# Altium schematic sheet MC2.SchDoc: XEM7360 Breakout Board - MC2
size C; Author: Nick Kettman; Organization: Opal Kelly; Address1: 13500 SW 72nd Ave Ste 100; Address2: Portland, OR 97223; Address4: http://www.opalkelly.com; DocumentNumber: xxx; Revision: 1; SheetNumber: 3; SheetTotal: 3; PageSetup: Record=PageOptions¦CenterHorizontal=True¦CenterVertical=True¦PrintScale=0.53¦XCorrection=1.00¦YCorrection=1.00¦PrintKind=0¦BorderSize=5000000¦LeftOffset=0¦BottomOffset=0¦Orientation=2¦PaperLength=1000¦PaperWidth=1000¦Scale=100¦PaperSource=7¦PrintQuality=-4¦MediaType=1¦DitherType=10¦PaperKind=Letter¦PrintScaleMode=1
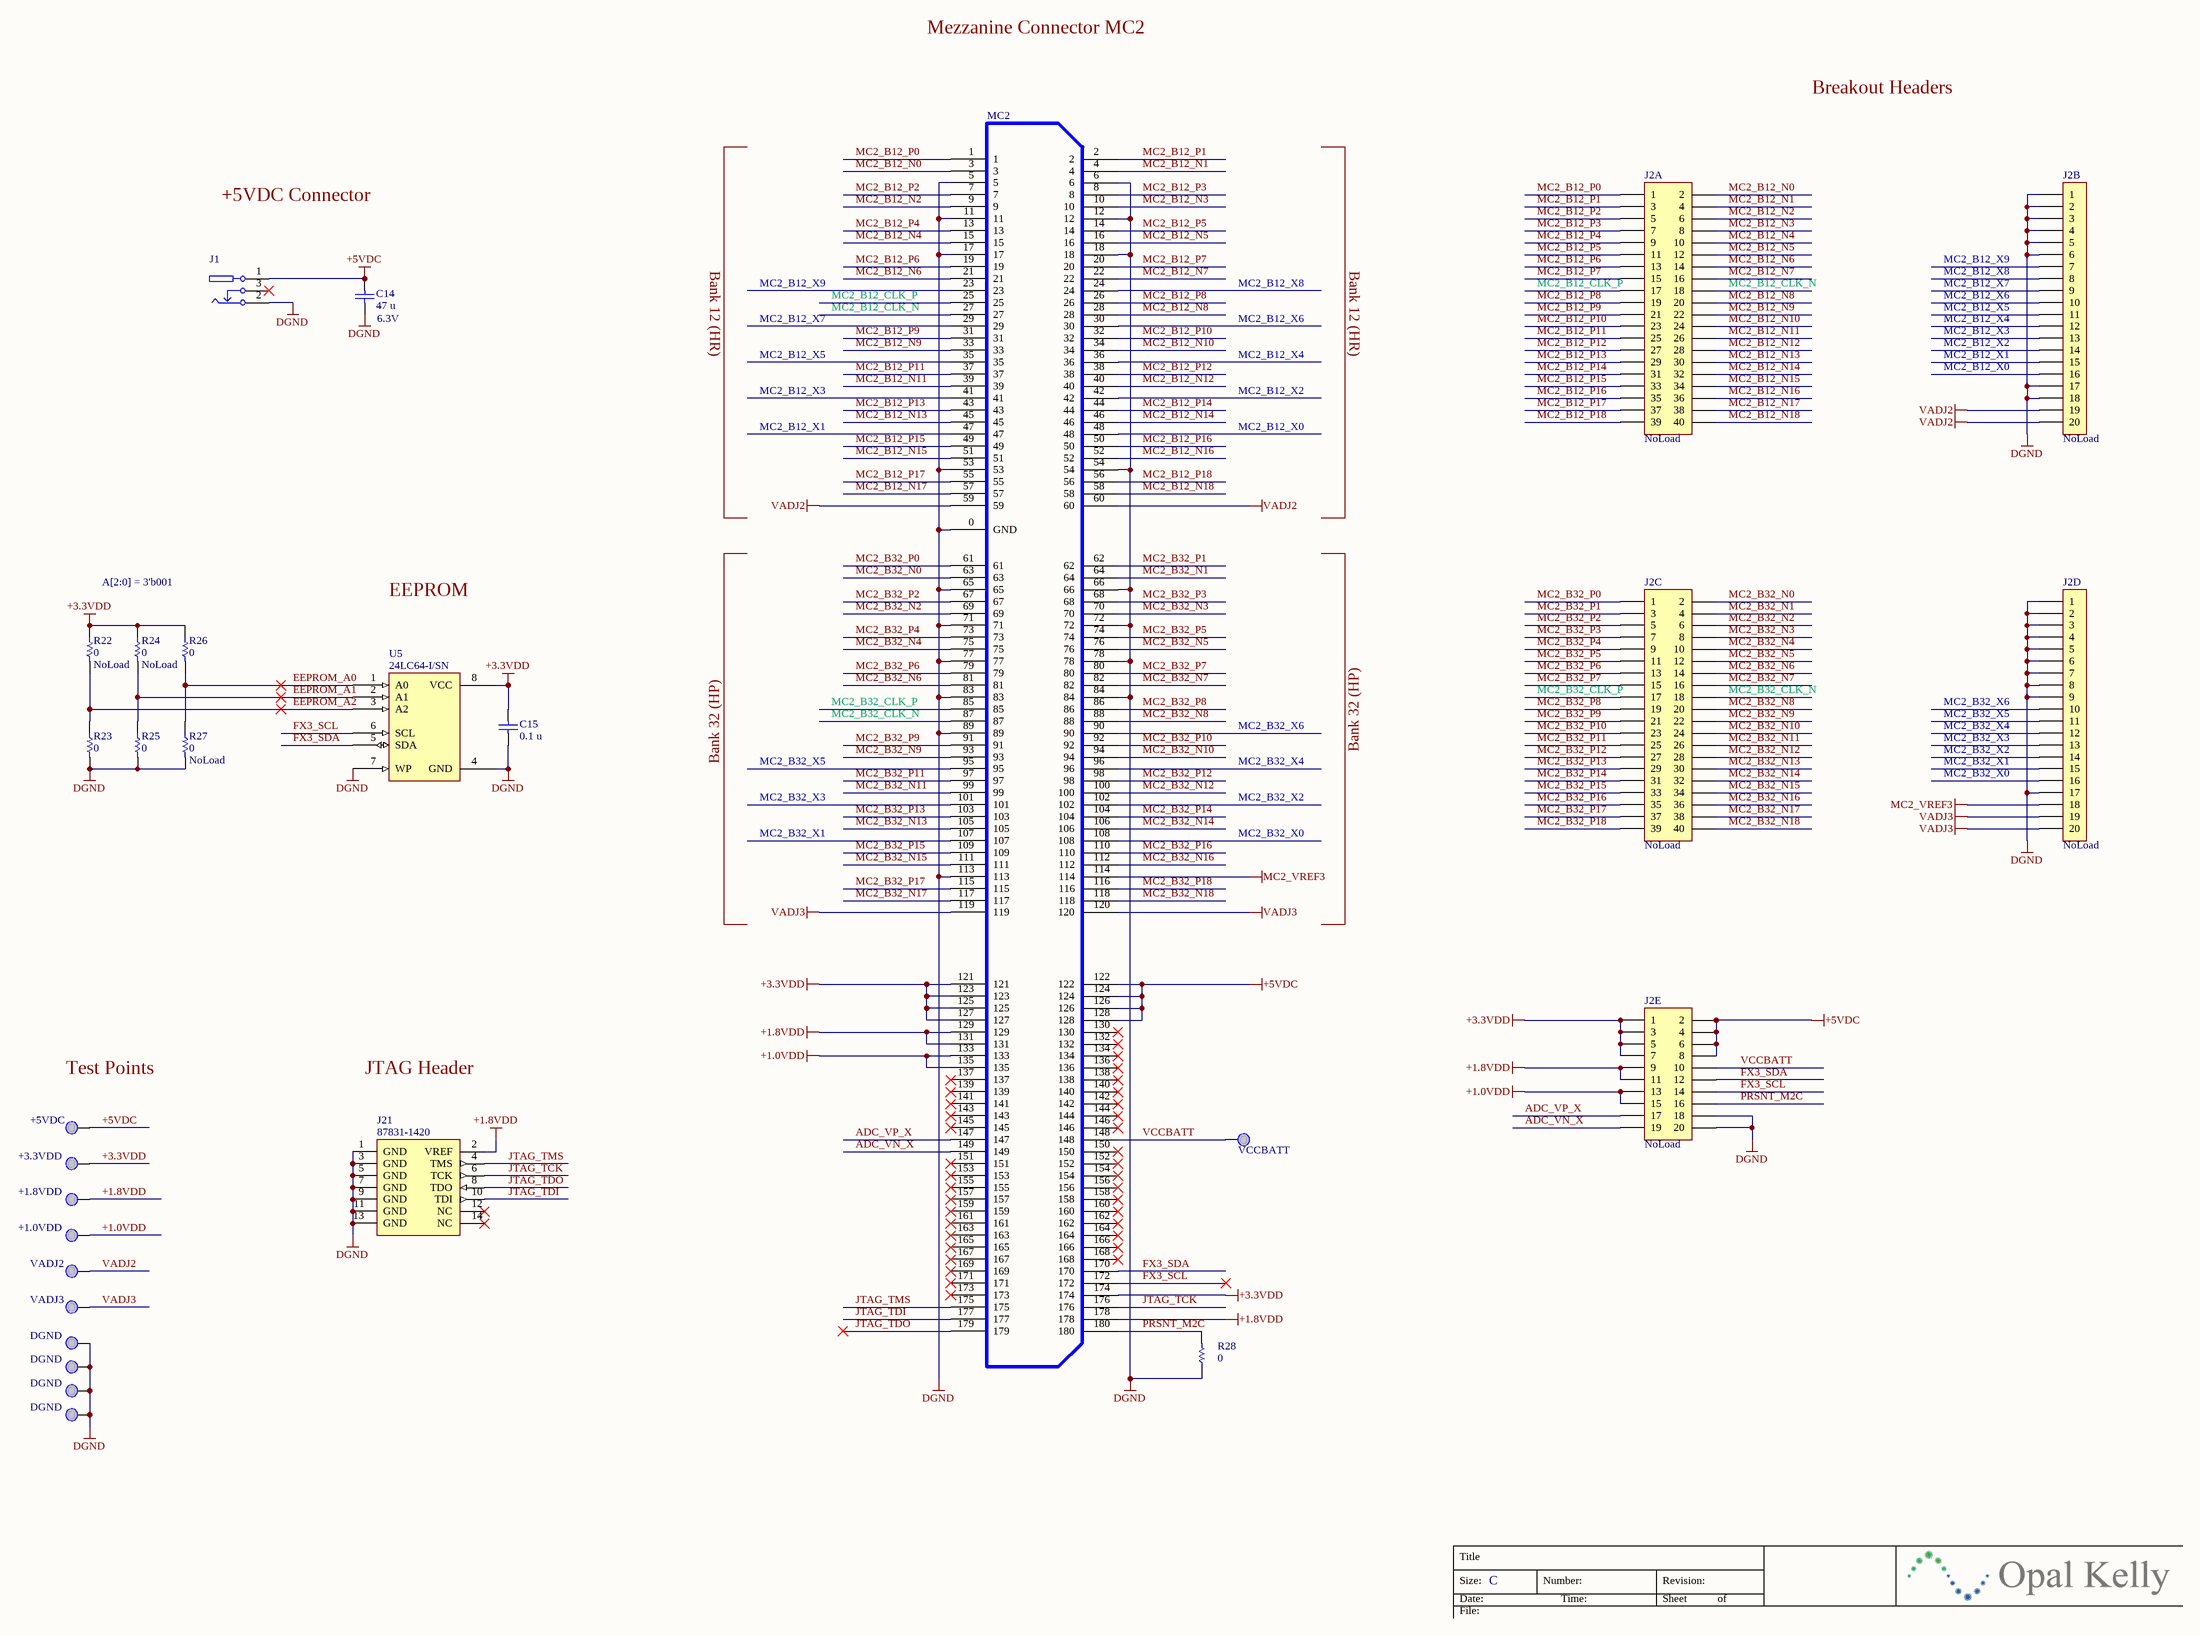
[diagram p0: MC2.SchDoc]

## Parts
C14  value 47 u  VoltageRating: 6.3V  [CAPC3216N]  (hidden comment: JMK316BJ476ML-T)
C15  value 0.1 u  [CAPC1005N]  (hidden comment: C0402C104K8PACTU)
J1  PJ-102AH  [CUI-PJ102A]  (value not drawn)
J2A  0877584016  [HDR2X20-2MM]  (value not drawn)
J2B  Header, 20-Pin, Single Row  [HDR1X20-2MM]  (value not drawn)
J2C  0877584016  [HDR2X20-2MM]  (value not drawn)
J2D  Header, 20-Pin, Single Row  [HDR1X20-2MM]  (value not drawn)
J2E  0877582016  [HDR2X10-2MM]  (value not drawn)
J21  87831-1420  [HDR2X7-2MM]
MC2  QTH-090-01-F-D-A  [QTH-090-01-X-D]  (value not drawn)
R22  value 0  [RESC1005N]  (hidden comment: CRCW04020000Z0ED)
R23  value 0  [RESC1005N]  (hidden comment: CRCW04020000Z0ED)
R24  value 0  [RESC1005N]  (hidden comment: CRCW04020000Z0ED)
R25  value 0  [RESC1005N]  (hidden comment: CRCW04020000Z0ED)
R26  value 0  [RESC1005N]  (hidden comment: CRCW04020000Z0ED)
R27  value 0  [RESC1005N]  (hidden comment: CRCW04020000Z0ED)
R28  value 0  [RESC1608N]  (hidden comment: CRCW06030000Z0EA)
TP2  +5VDC  [TP_MED]
TP3  +3.3VDD  [TP_MED]
TP4  +1.8VDD  [TP_MED]
TP5  +1.0VDD  [TP_MED]
TP6  VCCBATT  [TP_MED]
TP9  VADJ2  [TP_MED]
TP10  VADJ3  [TP_MED]
TP11  DGND  [TP_MED]
TP12  DGND  [TP_MED]
TP13  DGND  [TP_MED]
TP14  DGND  [TP_MED]
U5  24LC64-I/SN  [SO-G8]

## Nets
+1.0VDD: J2E.13 J2E.15 MC2.133 MC2.135 TP5.1(PIN)
+1.8VDD: J2E.9 J2E.11 J21.2(VREF) MC2.129 MC2.131 MC2.178 TP4.1(PIN)
+3.3VDD: C15.1 J2E.1 J2E.3 J2E.5 J2E.7 MC2.121 MC2.123 MC2.125 MC2.127 MC2.174 R22.1 R24.1 R26.1 TP3.1(PIN) U5.8(VCC)
+5VDC: C14.1 J1.1 J2E.2 J2E.4 J2E.6 J2E.8 MC2.122 MC2.124 MC2.126 MC2.128 TP2.1(PIN)
DGND: C14.2 C15.2 J1.2 J2B.1 J2B.2 J2B.3 J2B.4 J2B.5 J2B.6 J2B.17 J2B.18 J2D.1 J2D.2 J2D.3 J2D.4 J2D.5 J2D.6 J2D.7 J2D.8 J2D.9 J2D.17 J2E.18 J2E.20 J21.1(GND) J21.3(GND) J21.5(GND) J21.7(GND) J21.9(GND) J21.11(GND) J21.13(GND) MC2.0(GND) MC2.5 MC2.6 MC2.11 MC2.12 MC2.17 MC2.18 MC2.53 MC2.54 MC2.65 MC2.66 MC2.71 MC2.72 MC2.77 MC2.78 MC2.83 MC2.84 MC2.89 MC2.113 R23.2 R25.2 R27.2 R28.1 TP11.1(PIN) TP12.1(PIN) TP13.1(PIN) TP14.1(PIN) U5.4(GND) U5.7(WP)
MC2_VREF3: J2D.18 MC2.114
VADJ2: J2B.19 J2B.20 MC2.59 MC2.60 TP9.1(PIN)
VADJ3: J2D.19 J2D.20 MC2.119 MC2.120 TP10.1(PIN)
ADC_VN_X: J2E.19 MC2.149
ADC_VP_X: J2E.17 MC2.147
EEPROM_A0: R26.2 R27.1 U5.1(A0)
EEPROM_A1: R24.2 R25.1 U5.2(A1)
EEPROM_A2: R22.2 R23.1 U5.3(A2)
FX3_SCL: J2E.14 MC2.172 U5.6(SCL)
FX3_SDA: J2E.12 MC2.170 U5.5(SDA)
JTAG_TCK: J21.6(TCK) MC2.176
JTAG_TDI: J21.10(TDI) MC2.177
JTAG_TDO: J21.8(TDO) MC2.179
JTAG_TMS: J21.4(TMS) MC2.175
MC2_B12_CLK_N: J2A.18 MC2.27
MC2_B12_CLK_P: J2A.17 MC2.25
MC2_B12_N0: J2A.2 MC2.3
MC2_B12_N1: J2A.4 MC2.4
MC2_B12_N2: J2A.6 MC2.9
MC2_B12_N3: J2A.8 MC2.10
MC2_B12_N4: J2A.10 MC2.15
MC2_B12_N5: J2A.12 MC2.16
MC2_B12_N6: J2A.14 MC2.21
MC2_B12_N7: J2A.16 MC2.22
MC2_B12_N8: J2A.20 MC2.28
MC2_B12_N9: J2A.22 MC2.33
MC2_B12_N10: J2A.24 MC2.34
MC2_B12_N11: J2A.26 MC2.39
MC2_B12_N12: J2A.28 MC2.40
MC2_B12_N13: J2A.30 MC2.45
MC2_B12_N14: J2A.32 MC2.46
MC2_B12_N15: J2A.34 MC2.51
MC2_B12_N16: J2A.36 MC2.52
MC2_B12_N17: J2A.38 MC2.57
MC2_B12_N18: J2A.40 MC2.58
MC2_B12_P0: J2A.1 MC2.1
MC2_B12_P1: J2A.3 MC2.2
MC2_B12_P2: J2A.5 MC2.7
MC2_B12_P3: J2A.7 MC2.8
MC2_B12_P4: J2A.9 MC2.13
MC2_B12_P5: J2A.11 MC2.14
MC2_B12_P6: J2A.13 MC2.19
MC2_B12_P7: J2A.15 MC2.20
MC2_B12_P8: J2A.19 MC2.26
MC2_B12_P9: J2A.21 MC2.31
MC2_B12_P10: J2A.23 MC2.32
MC2_B12_P11: J2A.25 MC2.37
MC2_B12_P12: J2A.27 MC2.38
MC2_B12_P13: J2A.29 MC2.43
MC2_B12_P14: J2A.31 MC2.44
MC2_B12_P15: J2A.33 MC2.49
MC2_B12_P16: J2A.35 MC2.50
MC2_B12_P17: J2A.37 MC2.55
MC2_B12_P18: J2A.39 MC2.56
MC2_B12_X0: J2B.16 MC2.48
MC2_B12_X1: J2B.15 MC2.47
MC2_B12_X2: J2B.14 MC2.42
MC2_B12_X3: J2B.13 MC2.41
MC2_B12_X4: J2B.12 MC2.36
MC2_B12_X5: J2B.11 MC2.35
MC2_B12_X6: J2B.10 MC2.30
MC2_B12_X7: J2B.9 MC2.29
MC2_B12_X8: J2B.8 MC2.24
MC2_B12_X9: J2B.7 MC2.23
MC2_B32_CLK_N: J2C.18 MC2.87
MC2_B32_CLK_P: J2C.17 MC2.85
MC2_B32_N0: J2C.2 MC2.63
MC2_B32_N1: J2C.4 MC2.64
MC2_B32_N2: J2C.6 MC2.69
MC2_B32_N3: J2C.8 MC2.70
MC2_B32_N4: J2C.10 MC2.75
MC2_B32_N5: J2C.12 MC2.76
MC2_B32_N6: J2C.14 MC2.81
MC2_B32_N7: J2C.16 MC2.82
MC2_B32_N8: J2C.20 MC2.88
MC2_B32_N9: J2C.22 MC2.93
MC2_B32_N10: J2C.24 MC2.94
MC2_B32_N11: J2C.26 MC2.99
MC2_B32_N12: J2C.28 MC2.100
MC2_B32_N13: J2C.30 MC2.105
MC2_B32_N14: J2C.32 MC2.106
MC2_B32_N15: J2C.34 MC2.111
MC2_B32_N16: J2C.36 MC2.112
MC2_B32_N17: J2C.38 MC2.117
MC2_B32_N18: J2C.40 MC2.118
MC2_B32_P0: J2C.1 MC2.61
MC2_B32_P1: J2C.3 MC2.62
MC2_B32_P2: J2C.5 MC2.67
MC2_B32_P3: J2C.7 MC2.68
MC2_B32_P4: J2C.9 MC2.73
MC2_B32_P5: J2C.11 MC2.74
MC2_B32_P6: J2C.13 MC2.79
MC2_B32_P7: J2C.15 MC2.80
MC2_B32_P8: J2C.19 MC2.86
MC2_B32_P9: J2C.21 MC2.91
MC2_B32_P10: J2C.23 MC2.92
MC2_B32_P11: J2C.25 MC2.97
MC2_B32_P12: J2C.27 MC2.98
MC2_B32_P13: J2C.29 MC2.103
MC2_B32_P14: J2C.31 MC2.104
MC2_B32_P15: J2C.33 MC2.109
MC2_B32_P16: J2C.35 MC2.110
MC2_B32_P17: J2C.37 MC2.115
MC2_B32_P18: J2C.39 MC2.116
MC2_B32_X0: J2D.16 MC2.108
MC2_B32_X1: J2D.15 MC2.107
MC2_B32_X2: J2D.14 MC2.102
MC2_B32_X3: J2D.13 MC2.101
MC2_B32_X4: J2D.12 MC2.96
MC2_B32_X5: J2D.11 MC2.95
MC2_B32_X6: J2D.10 MC2.90
PRSNT_M2C: J2E.16 MC2.180 R28.2
VCCBATT: J2E.10 MC2.148 TP6.1(PIN)

Not connected (* = marked no-connect by the designer): J1 3*; J21 12(NC)* 14(NC)*; MC2 130* 132* 134* 136* 137* 138* 139* 140* 141* 142* 143* 144* 145* 146* 150* 151* 152* 153* 154* 155* 156* 157* 158* 159* 160* 161* 162* 163* 164* 165* 166* 167* 168* 169* 171* 173*

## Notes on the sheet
- Mezzanine Connector MC2
- Breakout Headers
- +5VDC Connector
- Bank 12 (HR)
- A[2:0] = 3'b001
- EEPROM
- Bank 32 (HP)
- Test Points
- JTAG Header
- Title
- Size:
- Date:
- File:
- C
- Number:
- Time:
- Revision:
- Sheet
- of

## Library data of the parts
C14 = 000570: Ceramic Capacitor; Manufacturer: Taiyo Yuden; partnumber: 000570; Description 2: 1206, 6.3V; ValueFloat: 4.7E-5; Tolerance (%): 20
C15 = 000070: Ceramic capacitor; Manufacturer: Kemet; partnumber: 000070; Description 2: SM-0402, 10%, 10v; ValueFloat: 1E-7; Tolerance (%): 10
J1 = 000356: DC power connector - high current; Manufacturer: CUI Inc.; partnumber: 000356; Description 2: 2.1mm / 5.5mm
J2A J2C = 000583: 2mm header, 20x2, thru-hole; Manufacturer: Molex; partnumber: 000583
J2B J2D = 001334: 2mm header, 20x1, thru-hole; PartNumber: 001334; Manufacturer: 3M; Manufacturer_PN: 951120-8622-AR; x_lifecycle_status: Production
J2E = 001338: 2mm header, 10x2, thru-hole; Manufacturer: Molex; partnumber: 001338
J21 = 000541: 2mm header, shrouded; Manufacturer: Molex; partnumber: 000541; Description 2: Dual-row, 14-pos, Xilinx JTAG compatible
MC2 = 000876: 0.5mm hi-speed, high-density header (Female); Manufacturer: Samtec; partnumber: 000876; Description 2: 180-pin, ground plane in middle
R22-R27 = 000755: Thick-film resistor; Manufacturer: Vishay; partnumber: 000755; Description 2: SM-0402, 1%, 1/16W; Tolerance (%): 1
R28 = 000411: Zero-ohm resistor; Manufacturer: Vishay; partnumber: 000411; Description 2: SM-0603, 1/10W, 20 mOhm max
TP2-TP6 TP9-TP14 = 000265: Testpoint; Manufacturer: Keystone Electronics; Manufacturer_PN: 5007; partnumber: 000265; Description 2: 0.063 in. diameter, compact, White
U5 = 000004: EEPROM; Manufacturer: Microchip; partnumber: 000004; Description 2: I2C, 8 kByte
